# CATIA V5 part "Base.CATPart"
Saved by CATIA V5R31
Part number: Base
Bounding box of the stored display mesh (mm): x -32 to 32, y 0 to 144, z 0 to 52
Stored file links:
  D:\PROJECTS\Project 2021\US EDITION\CATIA V5 6R 2021\Resources\Part Files\c12_catia_v5_6r2021_prt\c12_catia_v5-6r2021 figr_12-19\Base.CATPart
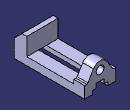
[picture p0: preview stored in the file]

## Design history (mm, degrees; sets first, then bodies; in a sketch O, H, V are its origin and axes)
Body1 (main body)
  Sketch1 on xy-plane, origin (0, 0, 0), H (1, 0, 0), V (0, 1, 0)
    point P1 (-32, 0)
    line L1 (-32, 0) -> (32, 0)
    line L2 (32, 0) -> (32, 144)
    line L3 (32, 144) -> (-32, 144)
    line L4 (-32, 144) -> (-32, 0)
    length L1 = 64
    length L2 = 144
    distance V L2 = 32
    coincidence: P1 H
    horizontal: L1 H, L3 H
    vertical: L2 V, L4 V
  Pad1: profile Sketch1, direction (0, 0, 1), length 16
  Sketch2 on face of Pad1, origin (32, 0, 0), H (0, 1, 0), V (0, 0, 1)
    point P1 (0, 16)
    line L1 (0, 16) -> (0, 36)
    point P2 (0, 36)
    line L2 (26, 52) -> (26, 16)
    line L3 (26, 16) -> (0, 16)
    reference projected line E1 (144, 16) -> (0, 16) from edge of Pad1
    line L4 (26, 52) -> (16, 52)
    point P5 (16, 52)
    line L5 (16, 52) -> (0, 36)
    length L2 = 36
    distance P5 P2 H = 16
    distance P5 P2 V = 16
    length L3 = 26
    coincidence: P1 V, E1 L3
    vertical: L1 V, L2 V
    horizontal: L3 H, L4 H
  Pad2: profile Sketch2, direction (-1, 0, 0), length 64
  Sketch3 on face of Pad1, origin (0, 144, 0), H (-1, 0, 0), V (0, 0, 1)
    line L1 (-32, 16) -> (-32, 24)
    point P2 (32, 24)
    line L2 (32, 24) -> (32, 16)
    line L3 (32, 16) -> (-32, 16)
    reference projected line E1 (32, 16) -> (-32, 16) from edge of Pad1
    line L4 (32, 24) -> (26, 24)
    point P4 (26, 24)
    line L5 (26, 24) -> (13.6777, 44.3018)
    point P5 (0, 52)
    line L6 (-13.6777, 44.3018) -> (-26, 24)
    point P6 (-26, 24)
    line L7 (-26, 24) -> (-32, 24)
    reference projected line E2 (32, 52) -> (-32, 52) from edge of Pad2
    reference projected line E3 (32, 16) -> (32, 52) from edge of Pad2
    reference projected line E4 (-32, 0) -> (-32, 16) from edge of Pad1
    arc A1 centre (0, 36) radius 16 from (13.6777, 44.3018) to (-13.6777, 44.3018) ccw
    point P8 (0, 36)
    reference projected line E5 (32, 52) -> (-32, 52) from edge of Pad2
    circle A2 centre (0, 36) radius 8
    distance H P2 = 24
    distance P6 P4 = 52
    distance P6 V = 26
    radius A1 = 16
    radius A2 = 8
    vertical: L1 V, L2 V
    horizontal: L3 H, L4 H, L7 H
    coincidence: L3 E1, P5 V, P6 L4, P5 E2, L2 E3, L1 E4, P8 V
    tangency: A1 E5, L6 A1, A1 L5
  Pad3: profile Sketch3, direction (0, -1, 0), length 22
  Fillet1: radius 3, on 2 edges
  Sketch4 on face of Pad1, origin (0, 144, 0), H (-1, 0, 0), V (0, 0, 1)
    point P1 (-16, 0)
    line L1 (-16, 0) -> (-16, 7)
    point P2 (-16, 7)
    line L2 (-16, 7) -> (-8, 7)
    point P3 (-8, 7)
    line L3 (-8, 7) -> (-8, 16)
    point P4 (-8, 16)
    line L4 (-8, 16) -> (0, 16)
    point P5 (0, 16)
    point P6 (16, 7)
    point P7 (16, 0)
    line L5 (16, 0) -> (16, 7)
    point P8 (8, 7)
    line L6 (16, 7) -> (8, 7)
    point P9 (8, 16)
    line L7 (8, 7) -> (8, 16)
    point P10 (0, 16)
    line L8 (8, 16) -> (0, 16)
    line L9 (-16, 0) -> (16, 0)
    point P11 (16, 0)
    distance L1 V = 16
    distance L3 V = 8
    distance H L4 = 16
    distance H L2 = 7
    coincidence: P1 H, P5 V, P7 P11, P5 P10
    vertical: L1 V, L3 V
    horizontal: L2 H, L4 H, L9 H
    symmetry: P2 P6 V, P1 P7 V, L1 L5 V, P3 P8 V, L2 L6 V, P4 P9 V, L3 L7 V, P5 P10 V, L4 L8 V
  Pocket1: profile Sketch4, direction (0, -1, 0), through (limit type 3)
  Sketch5 on face of Pad1, origin (0, 0, 0), H (1, 0, 0), V (0, -1, 0)
    circle A1 centre (22, -38) radius 3
    point P1 (22, -38)
    reference projected line E1 (32, 0) -> (-32, 0) from edge of Pad1
    radius A1 = 3
    distance P1 E1 = 38
    distance V P1 = 22
  Pocket2: profile Sketch5, direction (0, 0, 1), length 12
  RectPattern1: of Pocket2, direction 1 instances 2, spacing 70, along edge of Pad1, direction 2 instances 2, spacing 44, along edge of Pad1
